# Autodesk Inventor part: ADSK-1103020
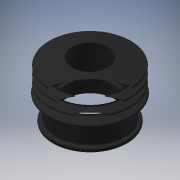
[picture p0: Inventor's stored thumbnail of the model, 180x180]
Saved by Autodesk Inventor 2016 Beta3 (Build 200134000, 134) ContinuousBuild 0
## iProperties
Shininess: 50.0
Length Units: 11272
Angle Units: 11279
Time Units: 11290
Mass Units: 11286
Length Display Precision: 4
Angle Display Precision: 2
Compacted: True
Created: 2000-09
Part Number: ADSK-1103020
Document SubType Name: Modeling
Description: DUST BOOT
Mass: 0.811722 g
Surface Area: 17.5384 cm^2
Volume: 0.872819 cm^3
Density: 0.93 g/cm^3
Material: Rubber
Appearance: Black
Density: 0.0
Volumn: 0.0
Area: 0.0
PropertySet Name: Model Information
Control State: 0
Master: False
Checked Out: False
Author: Autodesk, Inc.
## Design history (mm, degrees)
sketch "Sketch2"
  geometry: L1 (-7.556, -0.987)-(-7.555, -2.302); L2 (-7.428, -0.26)-(-12.947, -1.655); L3 (-3.726, 0)-(-3.726, -10.16); L4 (-9.439, -1.463)-(-7.556, -0.987); L5 (-6.708, -0.987)-(-6.708, -0.26); L6 (-6.708, -0.987)-(-6.708, -2.302); L7 (-6.708, -2.302)-(-7.555, -2.302); L8 (-6.708, -0.26)-(-7.428, -0.26); L9 (-10.074, -10.258)-(-8.804, -10.257); L10 (-8.804, -10.257)-(-8.806, -7.743); L11 (-8.806, -7.743)-(-9.432, -7.744); L12 (-9.432, -7.744)-(-9.439, -1.463); L13 (-10.074, -10.258)-(-10.072, -11.94); L14 (-10.072, -11.94)-(-11.389, -11.941); L15 (-11.389, -11.941)-(-11.389, -11.14); L16 (-11.389, -11.14)-(-10.659, -11.14); L17 (-10.659, -11.14)-(-10.662, -8.05); L18 (-10.662, -8.05)-(-11.393, -8.051); L19 (-12.947, -1.655)-(-9.718, -2.471); L20 (-9.718, -2.471)-(-12.947, -3.287); L21 (-12.947, -3.287)-(-9.718, -4.103); L22 (-9.718, -4.103)-(-12.947, -4.919); L23 (-12.947, -4.919)-(-9.718, -5.735); L24 (-9.718, -5.735)-(-12.947, -6.551); L25 (-12.947, -6.551)-(-11.394, -7.099); L26 (-11.393, -8.051)-(-11.394, -7.099); L27 (-11.395, -6.159)-(-11.395, -6.146)
  constraints: 54 end point, 15 parallel, 4 perpendicular, 1 collinear, 1 point on line
workaxis "Work Axis1"
node "Revolution1" dims "d0" = 90 deg
node "Fillet1" dims "d1" = 0.254
sketch "Sketch4"
  geometry: C1 r 2.981 at (3.726, 0) reference; C2 r 3.701 at (3.726, 0) reference; 1 further point
extrude "Extrusion2" cut sketch "Sketch4" stored distance "d7" = 25.4; taper "d8" = 0 deg
body "Solid1"
node "Projected Loop1"
